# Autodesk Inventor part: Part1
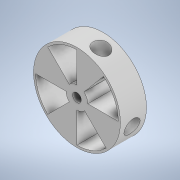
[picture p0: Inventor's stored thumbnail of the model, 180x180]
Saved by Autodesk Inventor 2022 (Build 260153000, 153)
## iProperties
Created: 2021-06
Part Number: Part1
Material: Generic
Document SubType Name: Modeling
Designer: USER
Density: 1 g/cm^3
Appearance: Default
Author: USER
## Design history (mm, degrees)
sketch "Sketch1" dims "d3" = 25
  geometry: L1 (12.5, 0)-(47.5, 0); L2 (0, 12.5)-(0, 47.5); L3 (-12.5, 0)-(-47.5, 0); L4 (0, -12.5)-(0, -47.5); L5 (9.426, 8.21)-(44.426, 8.21); L6 (0, 0)-(47.5, 0); L7 (8.035, 9.576)-(30.532, 36.387); L8 (0, 0)-(47.5, 0); L9 (-8.839, -8.839)-(-33.588, -33.588); L10 (0, 0)-(47.5, 0); L11 (-8.839, 8.839)-(-33.588, 33.588); L12 (8.839, -8.839)-(33.588, -33.588); C1 r 5 at (0, 0); A1 r 50 centre (0, 0) between (32.139, 38.302) and (50, 0); A2 r 47.5 centre (0, 0) between (47.5, 0) and (0, 47.5); 8 further points
  constraints: 24 end point, 7 point on circle, 5 horizontal, 4 coincident, 4 point on line, 3 centre point, 1 perpendicular, 11 other
  dimensions: "d0" = 100 diameter of A1; "d1" = 95 diameter of A2; "d2" = 10 diameter of C1; "d4" = 47.5 distance of L6.start L7.end; "d5" = 47.5 distance of L6.start L11.end; "d6" = 38.30222 vertical distance of A1.end A1.start; "d9" = 50 deg dimension on point (0, 0) A1.end A1.start
extrude "Extrusion1" new body sketch "Sketch1" stored distance "d7" = 30; taper "d8" = 0 deg
workplane "Work Plane1"
sketch "Sketch5"
  geometry: L1 (-12.5, 15)-(-12.5, -15) reference; C1 r 9 at (-12.5, 0); 1 further point
  constraints: 1 centre point, 1 midpoint
  dimensions: "d18" = 18 diameter of C1
extrude "Extrusion2" cut sketch "Sketch5" distance "d19" = 25; taper "d20" = 0 deg
workplane "Work Plane2"
sketch "Sketch6"
  geometry: L1 (-12.5, -15)-(-12.5, 15) reference; C1 r 9 at (-12.5, 0); 1 further point
  constraints: 1 centre point, 1 midpoint
  dimensions: "d22" = 18 diameter of C1
extrude "Extrusion3" cut sketch "Sketch6" distance "d23" = 20; taper "d24" = 0 deg
workplane "Work Plane3"
sketch "Sketch7"
  geometry: C1 r 9 at (10.751, 0); 1 further point
  constraints: 1 centre point
  dimensions: "d26" = 18 diameter of C1
extrude "Extrusion4" cut sketch "Sketch7" distance "d27" = 20; taper "d28" = 0 deg
workplane "Work Plane4"
workplane "Work Plane5"
sketch "Sketch10"
  geometry: L1 (12.5, 15)-(12.5, -15) reference; C1 r 9 at (12.5, 0); 1 further point
  constraints: 1 centre point, 1 midpoint
  dimensions: "d32" = 18 diameter of C1
extrude "Extrusion5" cut sketch "Sketch10" distance "d33" = 20; taper "d34" = 0 deg
body "Solid1"
